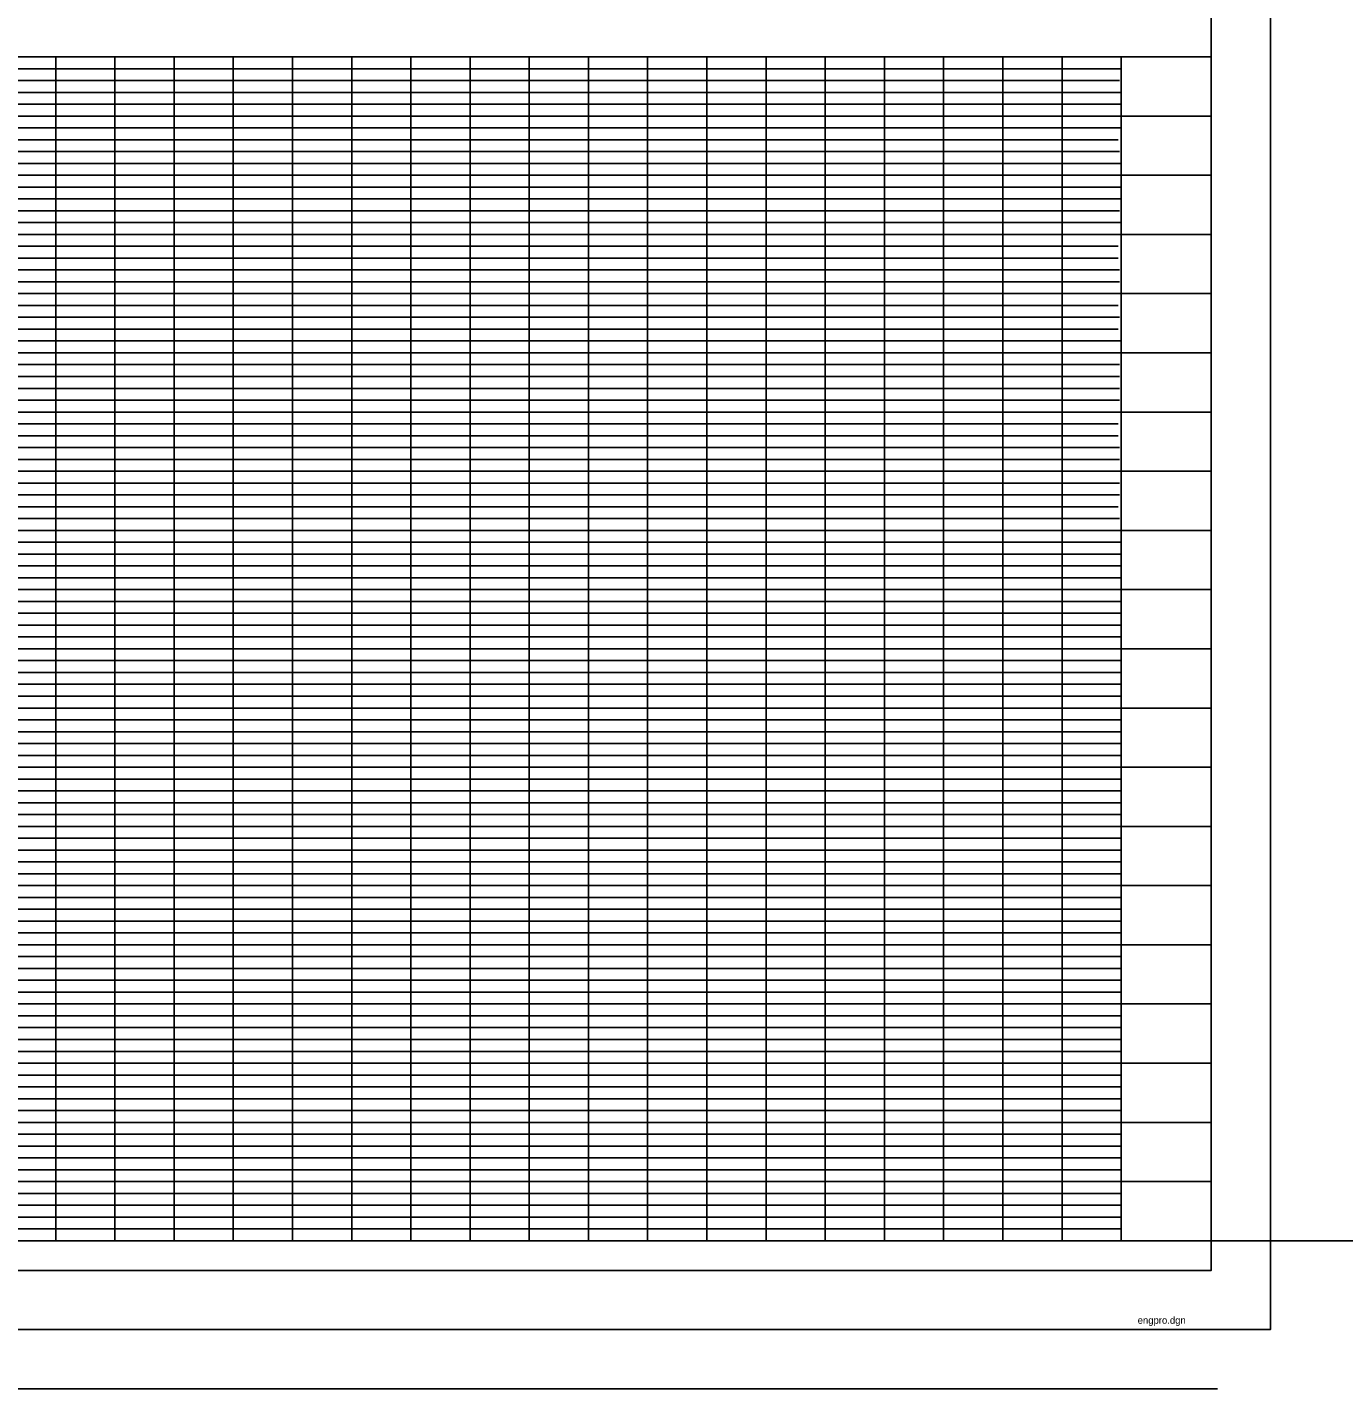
# Model space of a CAD drawing. Extents: x 49817 to 52200, y 49938 to 51088.
# Drawn here: x 51088 to 51644, y 49938 to 50513 of the extents above; entities that cross this region are included whole.
import ezdxf

# ---------------------------------------------------------------- set-up
doc = ezdxf.new("R2010")
doc.units = 0
for name, color, linetype in [('RD_GPK_Profile_Cell', 7, 'Continuous'), ('RD_SHT_Bndy', 7, 'Continuous'), ('RD_SHT_Iplotshp', 7, 'Continuous'), ('RD_SHT_MjGrid', 7, 'Continuous'), ('RD_SHT_MnGrid', 7, 'Continuous'), ('RD_SHT_SubGrid', 7, 'Continuous'), ('RD_SHT_TX', 7, 'Continuous')]:
    doc.layers.add(name, color=color, linetype=linetype)

msp = doc.modelspace()

# ---------------------------------------------------------------- linework, layer by layer
at = {"layer": 'RD_GPK_Profile_Cell'}
msp.add_line((50000, 50000), (52200, 50000), dxfattribs=at)
at = {"layer": 'RD_SHT_Bndy'}
for p, q in [((49913, 50500), (51588, 50500)), ((51550, 50500), (51550, 50000)), ((49913, 50000), (51588, 50000)), ((51590.65, 49962.5), (49830.65, 49962.5)), ((51590.65, 49937.5), (49830.65, 49937.5))]:
    msp.add_line(p, q, dxfattribs=at)
msp.add_lwpolyline([(49913.05, 51037.5), (51588, 51037.5), (51588, 49987.5), (49913.05, 49987.5)], close=True, dxfattribs=at)
at = {"layer": 'RD_SHT_Iplotshp'}
msp.add_lwpolyline([(49817.1, 51062.5), (51613, 51062.5), (51613, 49962.5), (49817.1, 49962.5)], close=True, dxfattribs=at)
at = {"layer": 'RD_SHT_MjGrid'}
for p, q in [((51100, 50500), (51100, 50000)), ((51150, 50500), (51150, 50000)), ((51200, 50500), (51200, 50000)), ((51250, 50500), (51250, 50000)), ((51300, 50500), (51300, 50000)), ((51350, 50500), (51350, 50000)), ((51400, 50500), (51400, 50000)), ((51450, 50500), (51450, 50000)), ((51500, 50500), (51500, 50000)), ((49913, 50450), (51588, 50450)), ((49913, 50400), (51588, 50400)), ((49913, 50350), (51588, 50350)), ((49913, 50300), (51588, 50300)), ((49913, 50250), (51588, 50250)), ((49913, 50200), (51588, 50200)), ((49913, 50150), (51588, 50150)), ((49913, 50100), (51588, 50100)), ((49913, 50050), (51588, 50050))]:
    msp.add_line(p, q, dxfattribs=at)
at = {"layer": 'RD_SHT_MnGrid'}
for p, q in [((51125, 50500), (51125, 50000)), ((51175, 50500), (51175, 50000)), ((51225, 50500), (51225, 50000)), ((51275, 50500), (51275, 50000)), ((51325, 50500), (51325, 50000)), ((51375, 50500), (51375, 50000)), ((51425, 50500), (51425, 50000)), ((51475, 50500), (51475, 50000)), ((51525, 50500), (51525, 50000)), ((49913, 50475), (51588, 50475)), ((49913, 50425), (51588, 50425)), ((49913, 50375), (51588, 50375)), ((49913, 50325), (51588, 50325)), ((49913, 50275), (51588, 50275)), ((49913, 50225), (51588, 50225)), ((49913, 50175), (51588, 50175)), ((49913, 50125), (51588, 50125)), ((49913, 50075), (51588, 50075)), ((49913, 50025), (51588, 50025))]:
    msp.add_line(p, q, dxfattribs=at)
at = {"layer": 'RD_SHT_SubGrid'}
for p, q in [((49950.05, 50495), (51549.8, 50495)), ((49950.05, 50490), (51549.25, 50490)), ((49950.05, 50485), (51549.8, 50485)), ((49950.1, 50480), (51549.8, 50480)), ((49950.05, 50470), (51549.8, 50470)), ((49950.05, 50465), (51548.75, 50465)), ((49950.05, 50460), (51549.25, 50460)), ((49950.05, 50455), (51549.8, 50455)), ((49950.05, 50445), (51549.8, 50445)), ((49950.05, 50440), (51549.8, 50440)), ((49950.05, 50435), (51549.25, 50435)), ((49950.05, 50430), (51549.8, 50430)), ((49950.05, 50420), (51548.75, 50420)), ((49950.05, 50415), (51548.75, 50415)), ((49950.05, 50410), (51549.25, 50410)), ((49950.05, 50405), (51549.25, 50405)), ((49950.05, 50395), (51548.75, 50395)), ((49950.05, 50390), (51549.25, 50390)), ((49950.05, 50385), (51548.75, 50385)), ((49950.1, 50380), (51549.8, 50380)), ((49950.05, 50370), (51549.25, 50370)), ((49950.05, 50365), (51549.25, 50365)), ((49950.05, 50360), (51549.25, 50360)), ((49950.05, 50355), (51549.25, 50355)), ((49950.15, 50345), (51548.75, 50345)), ((49950.15, 50340), (51548.75, 50340)), ((49950.1, 50335), (51549.25, 50335)), ((49950.1, 50330), (51549.25, 50330)), ((49950.05, 50320), (51549.25, 50320)), ((49950.05, 50315), (51549.25, 50315)), ((49950.05, 50310), (51548.75, 50310)), ((49950.05, 50305), (51549.25, 50305)), ((49950.05, 50305), (51549.25, 50305)), ((49950.05, 50295), (51549.8, 50295)), ((49950.05, 50290), (51549.8, 50290)), ((49950.05, 50285), (51549.8, 50285)), ((49950.05, 50280), (51549.8, 50280)), ((49950.05, 50270), (51549.8, 50270)), ((49950.05, 50265), (51549.8, 50265)), ((49950.05, 50260), (51549.8, 50260)), ((49950.05, 50255), (51549.8, 50255)), ((49950.05, 50245), (51549.85, 50245)), ((49950.05, 50240), (51549.85, 50240)), ((49950.05, 50235), (51549.85, 50235)), ((49950.05, 50230), (51549.85, 50230)), ((49950.05, 50220), (51549.85, 50220)), ((49950.05, 50215), (51549.85, 50215)), ((49950.05, 50210), (51549.85, 50210)), ((49950.05, 50205), (51549.85, 50205)), ((49950.05, 50195), (51549.85, 50195)), ((49950.05, 50190), (51549.85, 50190)), ((49950.05, 50185), (51549.85, 50185)), ((49950.05, 50180), (51549.85, 50180)), ((49950.05, 50170), (51549.85, 50170)), ((49950.1, 50170), (51549.85, 50170)), ((49950.05, 50165), (51549.85, 50165)), ((49950.1, 50160), (51549.6, 50160)), ((49950.1, 50155), (51549.6, 50155)), ((49950.05, 50140), (51549.95, 50140)), ((49950.1, 50145), (51549.8, 50145)), ((49950.05, 50135), (51549.95, 50135)), ((49950.1, 50130), (51549.95, 50130)), ((49950.05, 50120), (51549.95, 50120)), ((49950.05, 50115), (51549.95, 50115)), ((49950.05, 50110), (51549.95, 50110)), ((49950.1, 50105), (51549.95, 50105)), ((49950.05, 50095), (51549.95, 50095)), ((49950.05, 50090), (51549.95, 50090)), ((49950.05, 50085), (51549.95, 50085)), ((49950.05, 50080), (51549.85, 50080)), ((49950.1, 50070), (51549.6, 50070)), ((49950.05, 50065), (51549.85, 50065)), ((49950.05, 50060), (51549.85, 50060)), ((49950.05, 50055), (51549.85, 50055)), ((49950.15, 50045), (51549.85, 50045)), ((49950.05, 50040), (51549.85, 50040)), ((49950.05, 50035), (51549.85, 50035)), ((49950.05, 50030), (51549.85, 50030)), ((49950.15, 50020), (51549.85, 50020)), ((49950.15, 50015), (51549.85, 50015)), ((49950.15, 50010), (51549.85, 50010)), ((49950.15, 50005), (51549.85, 50005))]:
    msp.add_line(p, q, dxfattribs=at)

# ---------------------------------------------------------------- texts
at = {"layer": 'RD_SHT_TX'}
msp.add_text('engpro.dgn', height=3, dxfattribs=at).set_placement((51556.95, 49964.95))

doc.saveas('drawing.dxf')
